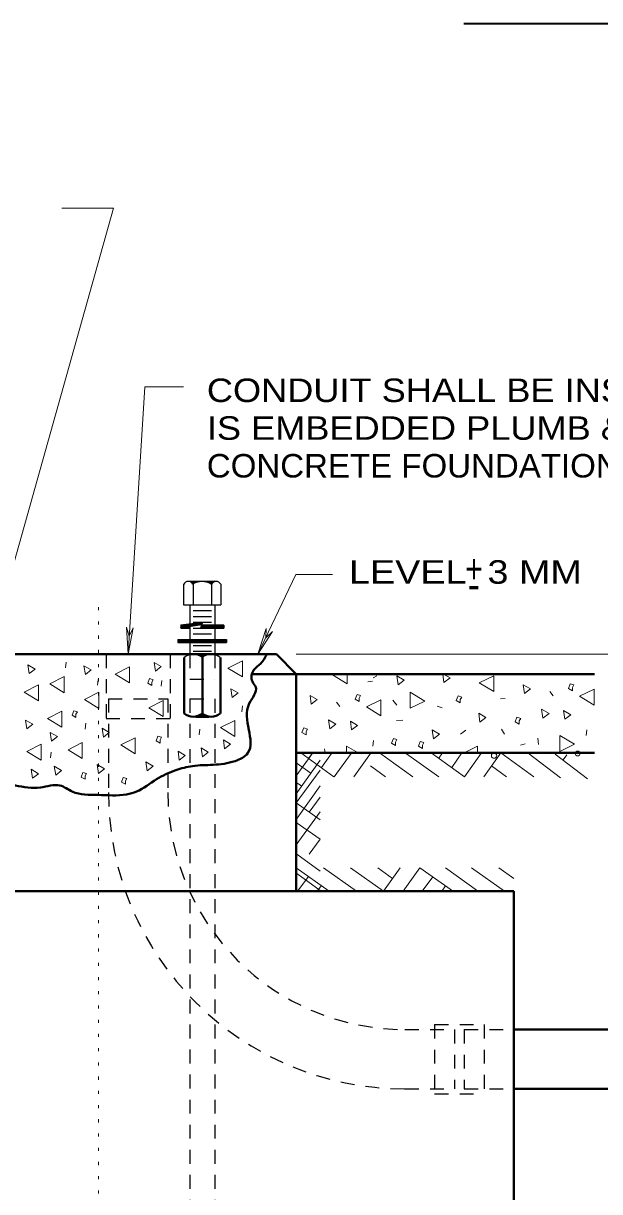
# Model space of a CAD drawing. Extents: x 312583 to 312854, y 144419 to 144597.
# Drawn here: x 312643.06 to 312661.67, y 144483.85 to 144521.63 of the extents above; entities that cross this region are included whole.
import ezdxf
from ezdxf.enums import TextEntityAlignment as Align

# ---------------------------------------------------------------- set-up
doc = ezdxf.new("R2010")
doc.units = 0
doc.header["$LTSCALE"] = 0.3
doc.linetypes.add('DOTTED', pattern=[1.5, 0.3, -1.2])
doc.linetypes.add('SHORT_DASHED', pattern=[2.7, 1.5, -1.2])
doc.layers.add('1', color=7, linetype='Continuous', lineweight=25)
doc.layers.add('2', color=7, linetype='Continuous', lineweight=13)

msp = doc.modelspace()

# ---------------------------------------------------------------- linework, layer by layer
at = {"layer": '1'}
for p, q in [((312648.2327, 144503.4947), (312648.2327, 144502.8277)), ((312648.386, 144503.5867), (312649.283, 144503.5867)), ((312648.5393, 144503.4947), (312648.5393, 144502.8277)), ((312649.1373, 144503.4947), (312649.1373, 144502.8277)), ((312649.4363, 144503.4947), (312649.4363, 144502.8277)), ((312648.2327, 144502.8277), (312649.4363, 144502.8277)), ((312648.432, 144502.8277), (312648.432, 144501.233)), ((312648.5393, 144502.6437), (312649.1373, 144502.6437)), ((312649.237, 144502.8277), (312649.237, 144501.233)), ((312648.1407, 144502.176), (312648.1407, 144502.0763)), ((312648.5393, 144502.452), (312649.1373, 144502.452)), ((312648.5393, 144502.268), (312649.1373, 144502.268)), ((312648.8077, 144502.176), (312649.5283, 144502.176)), ((312649.5283, 144502.1683), (312649.5283, 144502.0763)), ((312648.5393, 144502.0763), (312649.1373, 144502.0763)), ((312648.5393, 144501.8923), (312649.1373, 144501.8923)), ((312648.777, 144502.0763), (312649.5283, 144502.0763)), ((312648.0487, 144501.7007), (312649.6203, 144501.7007)), ((312648.0487, 144501.7007), (312648.0487, 144501.6087)), ((312648.0487, 144501.6777), (312649.6203, 144501.6777)), ((312648.0487, 144501.6547), (312649.6203, 144501.6547)), ((312648.0487, 144501.624), (312649.6203, 144501.624)), ((312648.0487, 144501.6087), (312649.6203, 144501.6087)), ((312648.5393, 144501.509), (312649.1373, 144501.509)), ((312648.5393, 144501.325), (312649.1373, 144501.325)), ((312649.6203, 144501.7007), (312649.6203, 144501.6087)), ((312648.432, 144501.233), (312649.237, 144501.233)), ((312648.5393, 144501.233), (312649.1297, 144501.233))]:
    msp.add_line(p, q, dxfattribs=at)
at = {"layer": '1', "linetype": 'DOTTED', "lineweight": 13}
msp.add_line((312645.488, 144469.9913), (312645.488, 144502.8813), dxfattribs=at)
at = {"layer": '1', "lineweight": 40}
for p, q in [((312639.738, 144501.233), (312651.238, 144501.233)), ((312648.248, 144501.1257), (312648.248, 144499.3163)), ((312648.8383, 144501.233), (312648.8383, 144499.209)), ((312649.421, 144501.1257), (312649.421, 144499.3163)), ((312651.238, 144501.233), (312651.8743, 144500.589)), ((312650.4483, 144500.589), (312651.8743, 144500.589)), ((312651.8743, 144500.589), (312651.8743, 144493.5663)), ((312651.8743, 144500.589), (312661.5113, 144500.589)), ((312651.8743, 144498.036), (312661.5113, 144498.036)), ((312632.0713, 144493.5663), (312658.9047, 144493.5663)), ((312658.9047, 144493.5663), (312658.9047, 144470.5663)), ((312658.9047, 144489.089), (312667.0467, 144489.089)), ((312658.9047, 144487.1723), (312667.0467, 144487.1723))]:
    msp.add_line(p, q, dxfattribs=at)
at = {"layer": '1', "linetype": 'SHORT_DASHED'}
for p, q in [((312645.7257, 144501.233), (312645.7257, 144499.1553)), ((312647.8033, 144501.233), (312647.8033, 144499.1553)), ((312648.432, 144501.233), (312648.432, 144500.4203)), ((312649.237, 144501.233), (312649.237, 144500.4203)), ((312648.432, 144500.4203), (312649.237, 144500.4203)), ((312645.8023, 144499.7917), (312645.8023, 144496.7557)), ((312645.8023, 144499.7917), (312647.719, 144499.7917)), ((312647.719, 144499.7917), (312647.719, 144496.7557)), ((312648.432, 144499.784), (312649.237, 144499.784)), ((312648.432, 144499.784), (312648.432, 144477.6273)), ((312649.237, 144499.784), (312649.237, 144477.6273)), ((312645.7257, 144499.1553), (312647.8033, 144499.1553)), ((312648.5393, 144499.209), (312649.1297, 144499.209)), ((312656.344, 144489.25), (312657.9463, 144489.25)), ((312657.9463, 144489.25), (312657.9463, 144487.0113)), ((312655.3857, 144489.089), (312656.988, 144489.089)), ((312656.988, 144489.089), (312656.988, 144487.1723)), ((312657.3023, 144489.089), (312657.3023, 144487.1723)), ((312657.3023, 144489.089), (312658.9047, 144489.089)), ((312655.3857, 144487.1723), (312656.988, 144487.1723)), ((312657.3023, 144487.1723), (312658.9047, 144487.1723))]:
    msp.add_line(p, q, dxfattribs=at)
at = {"layer": '1'}
for points in [[(312648.4243, 144503.5867), (312648.7617, 144503.579), (312648.7003, 144503.5713), (312648.662, 144503.5637), (312648.6007, 144503.5407), (312648.5393, 144503.4947), (312648.5163, 144503.533), (312648.4857, 144503.556), (312648.4397, 144503.579), (312648.731, 144503.579), (312648.6467, 144503.5637), (312648.5853, 144503.533), (312648.5393, 144503.5023), (312648.4933, 144503.5483), (312648.455, 144503.5713), (312648.6927, 144503.579), (312648.616, 144503.5483), (312648.5393, 144503.51), (312648.478, 144503.5713), (312648.6697, 144503.5713), (312648.5393, 144503.5177), (312648.4857, 144503.5637), (312648.6467, 144503.5713), (312648.5317, 144503.5253), (312648.501, 144503.5637), (312648.6237, 144503.5637), (312648.5393, 144503.5407), (312648.5163, 144503.556), (312648.593, 144503.5637), (312648.5393, 144503.5407), (312648.5317, 144503.556), (312648.5623, 144503.556), (312648.5393, 144503.5483)], [(312649.2447, 144503.5867), (312648.9073, 144503.579), (312648.9687, 144503.5713), (312649.007, 144503.5637), (312649.0683, 144503.5407), (312649.1297, 144503.4947), (312649.1527, 144503.533), (312649.1833, 144503.556), (312649.2293, 144503.579), (312648.938, 144503.579), (312649.0223, 144503.5637), (312649.0837, 144503.533), (312649.1297, 144503.5023), (312649.1757, 144503.5483), (312649.214, 144503.5713), (312648.9763, 144503.579), (312649.053, 144503.5483), (312649.1297, 144503.51), (312649.1987, 144503.5713), (312648.9993, 144503.5713), (312649.1297, 144503.5177), (312649.1833, 144503.5637), (312649.0223, 144503.5713), (312649.1373, 144503.5253), (312649.168, 144503.5637), (312649.0453, 144503.5637), (312649.1297, 144503.5407), (312649.1527, 144503.556), (312649.076, 144503.5637), (312649.1297, 144503.5407), (312649.1373, 144503.556), (312649.1067, 144503.556), (312649.1297, 144503.5483)], [(312648.1407, 144502.176), (312648.8383, 144502.268), (312648.777, 144502.0763)], [(312648.8077, 144502.176), (312648.1407, 144502.0763), (312648.432, 144502.0763)], [(312648.432, 144502.0763), (312648.1483, 144502.0917), (312648.156, 144502.1607), (312648.8153, 144502.2527), (312648.7923, 144502.1837), (312648.432, 144502.13), (312648.4243, 144502.0917), (312648.156, 144502.0993), (312648.1637, 144502.153), (312648.8, 144502.2373), (312648.7847, 144502.1913), (312648.4167, 144502.13), (312648.409, 144502.0993), (312648.1713, 144502.107), (312648.1713, 144502.1377), (312648.777, 144502.222), (312648.777, 144502.2067), (312648.4167, 144502.1377), (312648.3937, 144502.13), (312648.3247, 144502.1147), (312648.1867, 144502.1223), (312648.754, 144502.2143), (312648.2787, 144502.1223)], [(312648.7923, 144502.0917), (312649.513, 144502.0917), (312649.513, 144502.1607), (312648.8153, 144502.1607), (312648.7923, 144502.0993), (312649.5053, 144502.0993), (312649.4977, 144502.1453), (312648.823, 144502.1453), (312648.8077, 144502.107), (312649.49, 144502.1147), (312649.4823, 144502.13), (312649.4747, 144502.1377), (312648.8307, 144502.1377), (312648.823, 144502.1223), (312649.4747, 144502.1223)], [(312648.6237, 144501.2253), (312649.053, 144501.2253), (312649.007, 144501.2177), (312648.961, 144501.2023), (312648.9073, 144501.1793), (312648.8767, 144501.164), (312648.8383, 144501.141), (312648.8383, 144501.1333), (312648.754, 144501.187), (312648.685, 144501.21), (312648.639, 144501.2253), (312649.0223, 144501.2253), (312648.9917, 144501.2177), (312648.961, 144501.21), (312648.9073, 144501.1947), (312648.8613, 144501.1717), (312648.846, 144501.1563), (312648.8307, 144501.141), (312648.7617, 144501.187), (312648.685, 144501.2177), (312648.9687, 144501.2177), (312648.8997, 144501.1947), (312648.8383, 144501.1563), (312648.708, 144501.21), (312648.938, 144501.2177), (312648.8383, 144501.1487), (312648.7387, 144501.21), (312648.915, 144501.21), (312648.8383, 144501.1717), (312648.777, 144501.2023), (312648.892, 144501.2023), (312648.8383, 144501.187), (312648.7693, 144501.1947), (312648.8077, 144501.1717), (312648.823, 144501.2023), (312648.8307, 144501.164), (312648.8613, 144501.1947), (312648.8767, 144501.1947), (312648.892, 144501.2023)]]:
    msp.add_lwpolyline(points, dxfattribs=at)
at = {"layer": '1', "lineweight": 40}
msp.add_lwpolyline([(312648.6237, 144499.209), (312649.053, 144499.209), (312649.007, 144499.2167), (312648.961, 144499.232), (312648.9073, 144499.255), (312648.8767, 144499.2703), (312648.8383, 144499.301), (312648.8383, 144499.301), (312648.754, 144499.255), (312648.685, 144499.2243), (312648.639, 144499.2167), (312649.0223, 144499.209), (312648.9917, 144499.2167), (312648.961, 144499.2243), (312648.9073, 144499.2397), (312648.8613, 144499.2627), (312648.846, 144499.278), (312648.8307, 144499.2933), (312648.7617, 144499.2473), (312648.685, 144499.2167), (312648.9687, 144499.2167), (312648.8997, 144499.2397), (312648.8383, 144499.278), (312648.708, 144499.2243), (312648.938, 144499.2167), (312648.8383, 144499.2857), (312648.7387, 144499.2243), (312648.915, 144499.2243), (312648.8383, 144499.2703), (312648.777, 144499.232), (312648.892, 144499.232), (312648.8383, 144499.2473), (312648.7693, 144499.2397), (312648.8077, 144499.2627), (312648.823, 144499.2397), (312648.8307, 144499.278), (312648.8613, 144499.2473), (312648.8767, 144499.2397), (312648.892, 144499.2397)], dxfattribs=at)
at = {"layer": '1', "linetype": 'SHORT_DASHED'}
msp.add_lwpolyline([(312656.344, 144489.25), (312656.344, 144487.0113), (312657.9463, 144487.0113)], dxfattribs=at)
at = {"layer": '1'}
for centre, radius, start, end in [((312648.3856, 144503.4197), 0.1659, 25.60064, 154.39936), ((312648.8345, 144503.0632), 0.5224, 55.04559, 124.95441), ((312649.2835, 144503.4197), 0.1659, 25.60064, 154.39936), ((312648.5424, 144500.7751), 0.4545, 50.00693, 129.99306), ((312649.1266, 144500.7751), 0.4545, 50.00694, 129.99307)]:
    msp.add_arc(centre, radius, start, end, dxfattribs=at)
at = {"layer": '1', "lineweight": 40}
for centre, start, end in [((312648.5424, 144499.6613), 230.00694, 309.99307), ((312649.1266, 144499.6613), 230.00693, 309.99306)]:
    msp.add_arc(centre, 0.4545, start, end, dxfattribs=at)
at = {"layer": '1', "linetype": 'SHORT_DASHED'}
for radius in [9.5833, 7.6667]:
    msp.add_arc((312655.3889, 144496.7576), radius, 180, 270, dxfattribs=at)
at = {"layer": '1', "lineweight": 40}
msp.add_spline([(312640.4433, 144501.2407), (312640.4817, 144501.0643), (312640.451, 144500.865), (312640.451, 144500.4893), (312640.5737, 144500.1137), (312640.681, 144499.1477), (312640.7193, 144498.9177), (312640.8113, 144498.335), (312641.256, 144497.7063), (312641.9767, 144497.185), (312642.797, 144496.9857), (312643.6097, 144496.9167), (312644.2383, 144496.9857), (312644.637, 144496.7863), (312645.465, 144496.679), (312646.3927, 144496.6943), (312646.7147, 144496.7863), (312647.3587, 144497.185), (312647.9797, 144497.4763), (312648.524, 144497.6143), (312649.1833, 144497.6527), (312649.8963, 144497.7753), (312650.3103, 144498.036), (312650.341, 144498.7873), (312650.3563, 144499.6383), (312650.5633, 144500.1673), (312650.456, 144500.3437), (312650.502, 144500.7193), (312650.7243, 144500.9263), (312650.916, 144501.233)], degree=3, dxfattribs=at)
at = {"layer": '2', "lineweight": 35}
msp.add_line((312657.2919, 144521.6292), (312683.8367, 144521.6292), dxfattribs=at)
at = {"layer": '2'}
for p, q in [((312645.9633, 144515.654), (312642.59, 144503.5867)), ((312644.2997, 144515.654), (312645.9633, 144515.654)), ((312646.9753, 144509.881), (312646.4463, 144501.233)), ((312646.9753, 144509.881), (312648.225, 144509.881)), ((312651.859, 144503.809), (312650.6323, 144501.233)), ((312651.859, 144503.809), (312653.0473, 144503.809)), ((312646.3927, 144502.0993), (312646.477, 144501.8157)), ((312646.4463, 144501.233), (312646.3927, 144502.0993)), ((312646.4463, 144501.233), (312646.6073, 144502.084)), ((312646.6073, 144502.084), (312646.477, 144501.8157)), ((312650.6323, 144501.233), (312650.9007, 144502.061)), ((312650.6323, 144501.233), (312651.1, 144501.969)), ((312650.9007, 144502.061), (312650.8853, 144501.762)), ((312651.1, 144501.969), (312650.8853, 144501.762)), ((312644.4147, 144500.7883), (312644.4377, 144500.9723)), ((312651.8743, 144501.233), (312666.395, 144501.233)), ((312653.515, 144500.2747), (312653.515, 144500.589)), ((312656.6047, 144500.589), (312656.643, 144500.313)), ((312645.4497, 144500.2287), (312645.4727, 144500.4127)), ((312647.5043, 144500.198), (312647.5273, 144500.382)), ((312654.182, 144500.336), (312654.3353, 144500.359)), ((312654.3583, 144500.4663), (312654.481, 144500.5353)), ((312660.07, 144500.0217), (312660.1773, 144499.8837)), ((312650.111, 144499.37), (312650.134, 144499.5617)), ((312653.1777, 144499.6767), (312653.285, 144499.5387)), ((312654.9947, 144499.738), (312655.1173, 144499.577)), ((312656.4207, 144499.5463), (312656.5893, 144499.5003)), ((312658.4677, 144499.7917), (312658.621, 144499.7993)), ((312655.1097, 144499.0863), (312655.3167, 144499.094)), ((312645.051, 144498.8103), (312645.074, 144499.002)), ((312648.731, 144498.6263), (312648.754, 144498.8103)), ((312657.356, 144498.772), (312657.1797, 144498.6417)), ((312658.506, 144498.8103), (312658.598, 144498.6417)), ((312661.243, 144498.5957), (312661.266, 144498.7873)), ((312654.3507, 144498.2507), (312654.3737, 144498.4423)), ((312659.1193, 144498.289), (312659.265, 144498.3273)), ((312659.679, 144498.519), (312659.702, 144498.312)), ((312643.9317, 144497.8827), (312643.9547, 144498.0667)), ((312652.4033, 144498.036), (312651.8743, 144497.2923)), ((312653.0857, 144497.2693), (312652.02, 144498.036)), ((312652.388, 144498.0207), (312652.273, 144497.852)), ((312653.0167, 144498.0207), (312652.687, 144497.5607)), ((312652.7867, 144498.174), (312652.802, 144498.036)), ((312653.6453, 144498.0207), (312653.101, 144497.2617)), ((312653.4997, 144498.2583), (312653.4997, 144498.036)), ((312653.8677, 144498.036), (312653.4997, 144498.2583)), ((312654.274, 144498.0207), (312653.7297, 144497.2617)), ((312655.6387, 144497.2693), (312654.5653, 144498.036)), ((312656.482, 144497.2693), (312655.4393, 144498.013)), ((312657.31, 144497.2693), (312656.229, 144498.0437)), ((312656.597, 144498.036), (312656.482, 144497.8673)), ((312657.2257, 144498.036), (312656.896, 144497.5683)), ((312657.8543, 144498.036), (312657.31, 144497.2693)), ((312658.483, 144498.036), (312657.9387, 144497.2693)), ((312659.5487, 144497.2693), (312658.483, 144498.036)), ((312660.4073, 144497.231), (312659.3647, 144498.0283)), ((312661.2813, 144497.2003), (312660.2387, 144497.9977)), ((312660.6143, 144497.9747), (312660.4917, 144497.8137)), ((312652.641, 144497.7983), (312651.8667, 144496.7173)), ((312651.8743, 144497.714), (312652.342, 144497.3843)), ((312654.757, 144497.2693), (312654.274, 144497.622)), ((312658.667, 144497.2693), (312658.184, 144497.622)), ((312652.641, 144497.484), (312651.8743, 144496.4183)), ((312651.8743, 144497.0853), (312652.043, 144496.9703)), ((312652.641, 144496.9703), (312651.8973, 144495.9277)), ((312651.8743, 144496.4183), (312652.641, 144495.874)), ((312652.641, 144496.6023), (312652.2883, 144496.1193)), ((312652.641, 144496.127), (312651.8743, 144495.0613)), ((312651.8743, 144495.7897), (312652.641, 144495.2453)), ((312652.641, 144495.2453), (312652.2883, 144494.7623)), ((312651.8897, 144494.7623), (312652.6487, 144494.218)), ((312651.8667, 144494.3253), (312652.9323, 144493.5663)), ((312652.7483, 144494.3253), (312653.814, 144493.5663)), ((312653.6223, 144494.3253), (312654.6957, 144493.5663)), ((312654.504, 144494.3253), (312654.987, 144493.9803)), ((312654.6957, 144493.5663), (312655.2323, 144494.3253)), ((312655.3243, 144493.5663), (312655.861, 144494.3253)), ((312655.861, 144494.3253), (312656.9497, 144493.551)), ((312656.6967, 144494.3253), (312657.7317, 144493.5817)), ((312657.54, 144494.3253), (312658.6057, 144493.5663)), ((312658.4217, 144494.3253), (312658.9047, 144493.9803)), ((312651.8897, 144494.1337), (312652.6487, 144493.5893)), ((312651.928, 144493.574), (312652.2653, 144494.0417)), ((312655.9453, 144493.5663), (312656.2827, 144494.0263)), ((312652.5567, 144493.574), (312652.6793, 144493.7427)), ((312656.574, 144493.5663), (312656.6967, 144493.735))]:
    msp.add_line(p, q, dxfattribs=at)
for points in [[(312647.3203, 144500.681), (312647.512, 144500.8267), (312647.282, 144500.9647)], [(312650.134, 144500.497), (312650.134, 144501.0107), (312649.6663, 144500.773)], [(312643.2417, 144500.6043), (312643.441, 144500.75), (312643.2033, 144500.888)], [(312645.0587, 144500.5737), (312645.2503, 144500.7193), (312645.0127, 144500.8573)], [(312646.4847, 144500.3053), (312646.4847, 144500.819), (312646.017, 144500.589)], [(312643.5483, 144499.7227), (312643.5483, 144500.2363), (312643.0807, 144499.9987)], [(312644.3763, 144499.9833), (312644.3763, 144500.5047), (312643.9087, 144500.267)], [(312647.2053, 144500.3283), (312647.2513, 144500.405), (312647.1363, 144500.4433), (312647.075, 144500.29), (312647.2053, 144500.221)], [(312655.1633, 144500.2363), (312655.3627, 144500.3897), (312655.125, 144500.5277)], [(312658.253, 144500.0217), (312658.253, 144500.5353), (312657.7853, 144500.3053)], [(312659.2497, 144499.9603), (312659.4413, 144500.106), (312659.2037, 144500.244)], [(312660.7983, 144500.152), (312660.8443, 144500.2363), (312660.7217, 144500.267), (312660.668, 144500.1213), (312660.7983, 144500.0447)], [(312645.4957, 144499.4773), (312645.4957, 144499.9987), (312645.028, 144499.761)], [(312649.7967, 144499.83), (312649.996, 144499.9757), (312649.7583, 144500.1137)], [(312652.3573, 144499.6153), (312652.549, 144499.761), (312652.319, 144499.899)], [(312653.906, 144499.807), (312653.952, 144499.8913), (312653.837, 144499.922), (312653.7757, 144499.7763), (312653.906, 144499.6997)], [(312655.5543, 144499.9987), (312655.5543, 144499.485), (312656.022, 144499.715)], [(312657.172, 144499.7687), (312657.218, 144499.8453), (312657.103, 144499.8837), (312657.0417, 144499.7303), (312657.172, 144499.6613)], [(312661.496, 144499.5847), (312661.496, 144500.0983), (312661.0283, 144499.8683)], [(312647.5733, 144499.2167), (312647.5733, 144499.7303), (312647.1057, 144499.4927)], [(312654.6037, 144499.2397), (312654.6037, 144499.7533), (312654.1437, 144499.5233)], [(312659.84, 144499.163), (312660.0393, 144499.3087), (312659.8017, 144499.4543)], [(312643.165, 144498.818), (312643.3567, 144498.9637), (312643.1267, 144499.1017)], [(312644.2997, 144498.8717), (312644.2997, 144499.3853), (312643.832, 144499.1477)], [(312644.752, 144499.2857), (312644.8057, 144499.37), (312644.683, 144499.4007), (312644.6293, 144499.255), (312644.752, 144499.1783)], [(312649.8887, 144498.5727), (312649.8887, 144499.0863), (312649.421, 144498.8563)], [(312652.9553, 144498.818), (312653.147, 144498.9637), (312652.9093, 144499.1093)], [(312653.6607, 144498.7797), (312653.8523, 144498.9253), (312653.6223, 144499.0633)], [(312657.8083, 144499.0327), (312658, 144499.186), (312657.77, 144499.324)], [(312659.0733, 144499.0787), (312659.127, 144499.1553), (312659.0043, 144499.1937), (312658.9507, 144499.0403), (312659.0733, 144498.9713)], [(312660.5453, 144499.1247), (312660.7447, 144499.2703), (312660.507, 144499.4083)], [(312643.9623, 144498.4193), (312644.154, 144498.565), (312643.924, 144498.703)], [(312645.6413, 144498.5497), (312645.833, 144498.6953), (312645.603, 144498.8333)], [(312652.1887, 144498.7337), (312652.2347, 144498.8103), (312652.1197, 144498.8487), (312652.0583, 144498.6953), (312652.1887, 144498.6263)], [(312656.3057, 144498.496), (312656.4973, 144498.6417), (312656.2673, 144498.7797)], [(312643.6327, 144497.806), (312643.6327, 144498.3197), (312643.165, 144498.082)], [(312644.959, 144497.852), (312644.959, 144498.3733), (312644.499, 144498.1357)], [(312646.6687, 144498.013), (312646.6687, 144498.5267), (312646.201, 144498.2967)], [(312647.4737, 144498.4653), (312647.5197, 144498.542), (312647.4047, 144498.5803), (312647.3433, 144498.427), (312647.4737, 144498.358)], [(312649.559, 144498.174), (312649.7507, 144498.3197), (312649.5207, 144498.4653)], [(312655.079, 144498.3887), (312655.125, 144498.473), (312655.01, 144498.5037), (312654.9487, 144498.3503), (312655.079, 144498.2813)], [(312655.953, 144498.289), (312655.999, 144498.3733), (312655.8763, 144498.404), (312655.8227, 144498.2507), (312655.953, 144498.1817)], [(312660.392, 144498.5957), (312660.392, 144498.082), (312660.8597, 144498.3197)], [(312648.0947, 144497.806), (312648.2863, 144497.9517), (312648.0563, 144498.0897)], [(312648.8383, 144497.9133), (312649.03, 144498.059), (312648.8, 144498.197)], [(312644.1003, 144497.323), (312644.292, 144497.4687), (312644.0543, 144497.6067)], [(312645.4803, 144497.3767), (312645.6797, 144497.5223), (312645.442, 144497.6603)], [(312647.052, 144497.4533), (312647.2513, 144497.6067), (312647.0137, 144497.7447)], [(312643.349, 144497.2157), (312643.5483, 144497.3613), (312643.3107, 144497.507)], [(312645.051, 144497.2923), (312645.097, 144497.369), (312644.982, 144497.4073), (312644.9207, 144497.254), (312645.051, 144497.185)], [(312646.3543, 144497.1313), (312646.4003, 144497.208), (312646.2853, 144497.2463), (312646.224, 144497.093), (312646.3543, 144497.024)]]:
    msp.add_lwpolyline(points, close=True, dxfattribs=at)
for points in [[(312653.1163, 144500.589), (312653.0473, 144500.5583), (312653.515, 144500.2747)], [(312656.643, 144500.313), (312656.8423, 144500.4663), (312656.6277, 144500.589)], [(312657.7317, 144498.036), (312657.7317, 144498.2507), (312657.2947, 144498.036)]]:
    msp.add_lwpolyline(points, dxfattribs=at)
for centre, radius in [((312658.2641, 144497.9493), 0.0865), ((312660.9639, 144498.0197), 0.0784)]:
    msp.add_circle(centre, radius, dxfattribs=at)

# ---------------------------------------------------------------- texts
for s, width, p in [('CONDUIT SHALL BE INSTALLED SO THAT COUPLING', 1.15, (312648.984, 144509.3836)), ('IS EMBEDDED PLUMB & FLUSH WITH TOP OF', 1.15, (312648.984, 144508.1636)), ('CONCRETE FOUNDATION.', 1.05, (312648.984, 144506.9436)), ('LEVEL  3 MM', 1.2, (312653.5763, 144503.509))]:
    msp.add_text(s, height=0.76, dxfattribs=dict(at, width=width)).set_placement(p)
at = {"layer": '2', "width": 0.8}
msp.add_text('+', height=0.92, dxfattribs=at).set_placement((312657.618, 144503.5381), align=Align.CENTER)
at = {"layer": '2'}
msp.add_text('-', height=0.92, dxfattribs=at).set_placement((312657.6103, 144503.0243), align=Align.CENTER)

doc.saveas('drawing.dxf')
